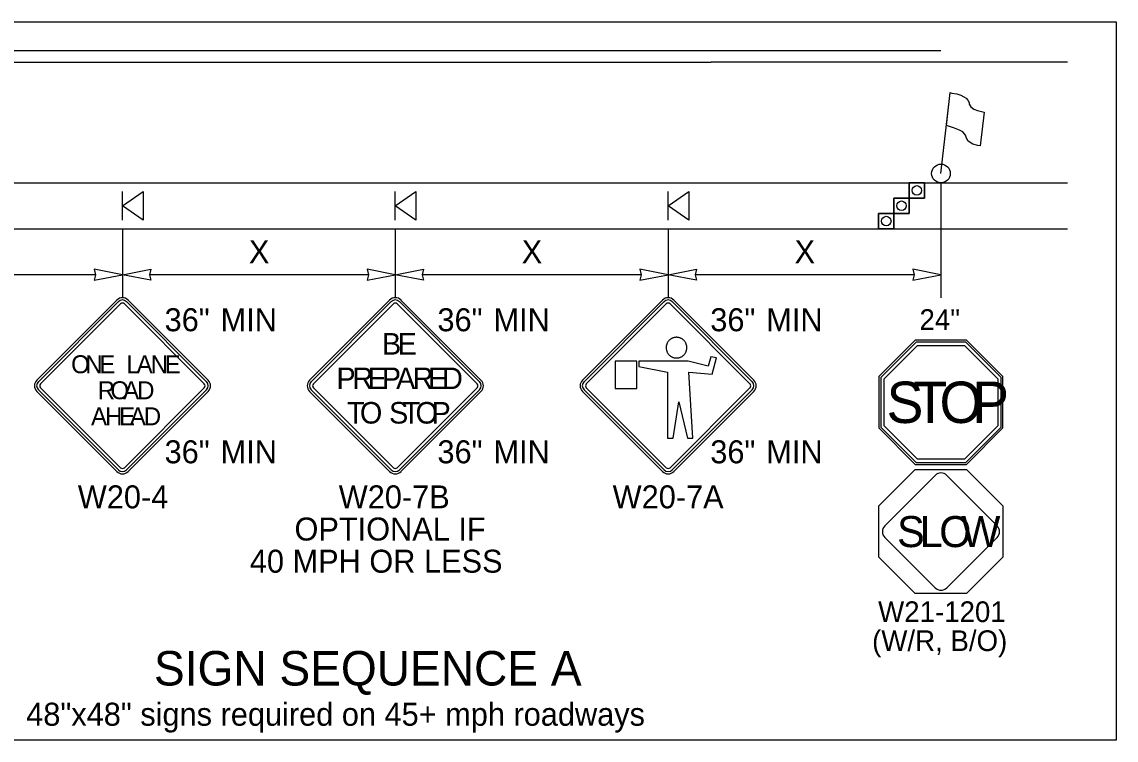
# Model space of a CAD drawing. Extents: x 99999.1 to 100095.7, y 99995 to 100010.7.
# Drawn here: x 100021.34 to 100025.15, y 100006.18 to 100008.68 of the extents above; entities that cross this region are included whole.
import ezdxf

# ---------------------------------------------------------------- set-up
doc = ezdxf.new("R2010")
doc.units = 0
for name, color, linetype in [('RD_ED_ShoulderPavedEdge', 7, 'Continuous'), ('RD_MK_LineDblYellowCenter', 7, 'Continuous'), ('RD_MK_LineEdgeWhite', 7, 'Continuous'), ('RD_MK_LineNoPass', 7, 'Continuous'), ('RD_MK_LineSkipCenter', 7, 'Continuous'), ('SH_DE_DetailHeading2Text', 7, 'Continuous'), ('TR_SN_ConstructionSigns', 7, 'Continuous'), ('TR_WZ_FlaggingStation', 7, 'Continuous'), ('TR_WZ_PortableSignMountBlk-Org', 7, 'Continuous'), ('TR_WZ_TrafficCone', 7, 'Continuous'), ('TR_WZ_WorkZoneDetails', 7, 'Continuous'), ('TR_WZ_WorkZoneTextCurrent', 7, 'Continuous')]:
    doc.layers.add(name, color=color, linetype=linetype)

msp = doc.modelspace()

# ---------------------------------------------------------------- linework, layer by layer
at = {"layer": 'RD_ED_ShoulderPavedEdge'}
msp.add_line((100020.3, 100007.9602), (100024.9804, 100007.9602), dxfattribs=at)
at = {"layer": 'RD_MK_LineDblYellowCenter'}
for p, q in [((100020.3, 100008.5802), (100023.7402, 100008.5802)), ((100020.3, 100008.5402), (100023.7402, 100008.5402))]:
    msp.add_line(p, q, dxfattribs=at)
at = {"layer": 'RD_MK_LineEdgeWhite'}
msp.add_line((100020.3, 100008.1202), (100024.9804, 100008.1202), dxfattribs=at)
at = {"layer": 'RD_MK_LineNoPass'}
msp.add_line((100023.7402, 100008.5802), (100024.5402, 100008.5802), dxfattribs=at)
at = {"layer": 'RD_MK_LineSkipCenter'}
msp.add_lwpolyline([(100024.9804, 100008.5402), (100023.7402, 100008.5402)], dxfattribs=at)
at = {"layer": 'TR_SN_ConstructionSigns'}
for p, q in [((100021.6703, 100007.712), (100021.3919, 100007.4336)), ((100021.9885, 100007.4336), (100021.71, 100007.712)), ((100022.6203, 100007.712), (100022.3419, 100007.4336)), ((100022.9385, 100007.4336), (100022.66, 100007.712)), ((100023.5703, 100007.712), (100023.2919, 100007.4336)), ((100023.8885, 100007.4336), (100023.61, 100007.712)), ((100021.6758, 100007.7065), (100021.3974, 100007.428)), ((100021.4051, 100007.4203), (100021.6835, 100007.6987)), ((100021.6968, 100007.6987), (100021.9752, 100007.4203)), ((100021.9829, 100007.428), (100021.7045, 100007.7065)), ((100022.6258, 100007.7065), (100022.3474, 100007.428)), ((100022.3551, 100007.4203), (100022.6335, 100007.6987)), ((100022.6468, 100007.6987), (100022.9252, 100007.4203)), ((100022.9329, 100007.428), (100022.6545, 100007.7065)), ((100023.5758, 100007.7065), (100023.2974, 100007.428)), ((100023.3051, 100007.4203), (100023.5835, 100007.6987)), ((100023.5968, 100007.6987), (100023.8752, 100007.4203)), ((100023.8829, 100007.428), (100023.6045, 100007.7065)), ((100023.5858, 100007.5595), (100023.5852, 100007.5577)), ((100023.5865, 100007.5613), (100023.5858, 100007.5595)), ((100023.5873, 100007.563), (100023.5865, 100007.5613)), ((100023.5883, 100007.5647), (100023.5873, 100007.563)), ((100023.5894, 100007.5664), (100023.5883, 100007.5647)), ((100023.5904, 100007.5679), (100023.5894, 100007.5664)), ((100023.5916, 100007.5694), (100023.5904, 100007.5679)), ((100023.5929, 100007.5709), (100023.5916, 100007.5694)), ((100023.5942, 100007.5722), (100023.5929, 100007.5709)), ((100023.5956, 100007.5735), (100023.5942, 100007.5722)), ((100023.5971, 100007.5747), (100023.5956, 100007.5735)), ((100023.5986, 100007.5759), (100023.5971, 100007.5747)), ((100023.6002, 100007.5769), (100023.5986, 100007.5759)), ((100023.6019, 100007.5779), (100023.6002, 100007.5769)), ((100023.6036, 100007.5788), (100023.6019, 100007.5779)), ((100023.6053, 100007.5796), (100023.6036, 100007.5788)), ((100023.6071, 100007.5803), (100023.6053, 100007.5796)), ((100023.6089, 100007.5809), (100023.6071, 100007.5803)), ((100023.6108, 100007.5814), (100023.6089, 100007.5809)), ((100023.6127, 100007.5818), (100023.6108, 100007.5814)), ((100023.6146, 100007.5821), (100023.6127, 100007.5818)), ((100023.6164, 100007.5823), (100023.6146, 100007.5821)), ((100023.6184, 100007.5824), (100023.6164, 100007.5823)), ((100023.6203, 100007.5824), (100023.6184, 100007.5824)), ((100023.6222, 100007.5823), (100023.6203, 100007.5824)), ((100023.6241, 100007.5821), (100023.6222, 100007.5823)), ((100023.626, 100007.5818), (100023.6241, 100007.5821)), ((100023.6279, 100007.5814), (100023.626, 100007.5818)), ((100023.6297, 100007.5809), (100023.6279, 100007.5814)), ((100023.6316, 100007.5803), (100023.6297, 100007.5809)), ((100023.6333, 100007.5796), (100023.6316, 100007.5803)), ((100023.6351, 100007.5788), (100023.6333, 100007.5796)), ((100023.6368, 100007.5779), (100023.6351, 100007.5788)), ((100023.6385, 100007.5769), (100023.6368, 100007.5779)), ((100023.64, 100007.5759), (100023.6385, 100007.5769)), ((100023.6416, 100007.5747), (100023.64, 100007.5759)), ((100023.643, 100007.5735), (100023.6416, 100007.5747)), ((100023.6445, 100007.5722), (100023.643, 100007.5735)), ((100023.6458, 100007.5709), (100023.6445, 100007.5722)), ((100023.647, 100007.5694), (100023.6458, 100007.5709)), ((100023.6482, 100007.5679), (100023.647, 100007.5694)), ((100023.6494, 100007.5664), (100023.6482, 100007.5679)), ((100023.6504, 100007.5647), (100023.6494, 100007.5664)), ((100023.6513, 100007.563), (100023.6504, 100007.5647)), ((100023.6521, 100007.5613), (100023.6513, 100007.563)), ((100023.6529, 100007.5595), (100023.6521, 100007.5613)), ((100023.6535, 100007.5577), (100023.6529, 100007.5595)), ((100024.4506, 100007.5722), (100024.3241, 100007.4457)), ((100024.4534, 100007.5655), (100024.3308, 100007.4429)), ((100024.6295, 100007.5722), (100024.4506, 100007.5722)), ((100024.6267, 100007.5655), (100024.4534, 100007.5655)), ((100024.7493, 100007.4429), (100024.6267, 100007.5655)), ((100024.7561, 100007.4457), (100024.6295, 100007.5722)), ((100023.5835, 100007.5502), (100023.5833, 100007.5483)), ((100023.5833, 100007.5483), (100023.5833, 100007.5464)), ((100023.5833, 100007.5464), (100023.5833, 100007.5445)), ((100023.5833, 100007.5445), (100023.5835, 100007.5426)), ((100023.5838, 100007.5522), (100023.5835, 100007.5502)), ((100023.5835, 100007.5426), (100023.5838, 100007.5407)), ((100023.5842, 100007.554), (100023.5838, 100007.5522)), ((100023.5838, 100007.5407), (100023.5842, 100007.5388)), ((100023.5846, 100007.5559), (100023.5842, 100007.554)), ((100023.5842, 100007.5388), (100023.5846, 100007.5369)), ((100023.5852, 100007.5577), (100023.5846, 100007.5559)), ((100023.5846, 100007.5369), (100023.5852, 100007.5351)), ((100023.5852, 100007.5351), (100023.5858, 100007.5333)), ((100023.5858, 100007.5333), (100023.5865, 100007.5315)), ((100023.5865, 100007.5315), (100023.5873, 100007.5298)), ((100023.5873, 100007.5298), (100023.5883, 100007.5281)), ((100023.5883, 100007.5281), (100023.5894, 100007.5265)), ((100023.5894, 100007.5265), (100023.5904, 100007.5249)), ((100023.5904, 100007.5249), (100023.5916, 100007.5234)), ((100023.5916, 100007.5234), (100023.5929, 100007.522)), ((100023.5929, 100007.522), (100023.5942, 100007.5206)), ((100023.5942, 100007.5206), (100023.5956, 100007.5193)), ((100023.643, 100007.5193), (100023.6445, 100007.5206)), ((100023.6445, 100007.5206), (100023.6458, 100007.522)), ((100023.6458, 100007.522), (100023.647, 100007.5234)), ((100023.647, 100007.5234), (100023.6482, 100007.5249)), ((100023.6482, 100007.5249), (100023.6494, 100007.5265)), ((100023.6494, 100007.5265), (100023.6504, 100007.5281)), ((100023.6504, 100007.5281), (100023.6513, 100007.5298)), ((100023.6513, 100007.5298), (100023.6521, 100007.5315)), ((100023.6521, 100007.5315), (100023.6529, 100007.5333)), ((100023.6529, 100007.5333), (100023.6535, 100007.5351)), ((100023.6541, 100007.5559), (100023.6535, 100007.5577)), ((100023.6535, 100007.5351), (100023.6541, 100007.5369)), ((100023.6545, 100007.554), (100023.6541, 100007.5559)), ((100023.6541, 100007.5369), (100023.6545, 100007.5388)), ((100023.6549, 100007.5522), (100023.6545, 100007.554)), ((100023.6545, 100007.5388), (100023.6549, 100007.5407)), ((100023.6552, 100007.5502), (100023.6549, 100007.5522)), ((100023.6549, 100007.5407), (100023.6552, 100007.5426)), ((100023.6553, 100007.5483), (100023.6552, 100007.5502)), ((100023.6552, 100007.5426), (100023.6553, 100007.5445)), ((100023.6554, 100007.5464), (100023.6553, 100007.5483)), ((100023.6553, 100007.5445), (100023.6554, 100007.5464)), ((100024.3421, 100007.4383), (100024.4581, 100007.5542)), ((100024.4581, 100007.5542), (100024.6221, 100007.5542)), ((100024.6221, 100007.5542), (100024.7381, 100007.4383)), ((100023.4059, 100007.4991), (100023.4059, 100007.4044)), ((100023.4812, 100007.4991), (100023.4059, 100007.4991)), ((100023.4812, 100007.4044), (100023.4812, 100007.4991)), ((100023.6596, 100007.4991), (100023.4882, 100007.4991)), ((100023.4882, 100007.4991), (100023.4882, 100007.481)), ((100023.5956, 100007.5193), (100023.5971, 100007.5181)), ((100023.5971, 100007.5181), (100023.5986, 100007.5169)), ((100023.5986, 100007.5169), (100023.6002, 100007.5159)), ((100023.6002, 100007.5159), (100023.6019, 100007.5149)), ((100023.6019, 100007.5149), (100023.6036, 100007.514)), ((100023.6036, 100007.514), (100023.6053, 100007.5132)), ((100023.6053, 100007.5132), (100023.6071, 100007.5125)), ((100023.6071, 100007.5125), (100023.6089, 100007.5119)), ((100023.6089, 100007.5119), (100023.6108, 100007.5114)), ((100023.6108, 100007.5114), (100023.6127, 100007.511)), ((100023.6127, 100007.511), (100023.6146, 100007.5107)), ((100023.6146, 100007.5107), (100023.6164, 100007.5105)), ((100023.6164, 100007.5105), (100023.6184, 100007.5104)), ((100023.6184, 100007.5104), (100023.6203, 100007.5104)), ((100023.6203, 100007.5104), (100023.6222, 100007.5105)), ((100023.6222, 100007.5105), (100023.6241, 100007.5107)), ((100023.6241, 100007.5107), (100023.626, 100007.511)), ((100023.626, 100007.511), (100023.6279, 100007.5114)), ((100023.6279, 100007.5114), (100023.6297, 100007.5119)), ((100023.6297, 100007.5119), (100023.6316, 100007.5125)), ((100023.6316, 100007.5125), (100023.6333, 100007.5132)), ((100023.6333, 100007.5132), (100023.6351, 100007.514)), ((100023.6351, 100007.514), (100023.6368, 100007.5149)), ((100023.6368, 100007.5149), (100023.6385, 100007.5159)), ((100023.6385, 100007.5159), (100023.64, 100007.5169)), ((100023.64, 100007.5169), (100023.6416, 100007.5181)), ((100023.6416, 100007.5181), (100023.643, 100007.5193)), ((100023.7291, 100007.482), (100023.6596, 100007.4991)), ((100023.7388, 100007.5148), (100023.7291, 100007.482)), ((100023.7588, 100007.5112), (100023.7388, 100007.5148)), ((100023.7438, 100007.4544), (100023.7588, 100007.5112)), ((100023.4882, 100007.481), (100023.5877, 100007.4612)), ((100023.5877, 100007.4612), (100023.5877, 100007.2309)), ((100023.6759, 100007.2309), (100023.6628, 100007.4613)), ((100023.6628, 100007.4613), (100023.7438, 100007.4544)), ((100024.3241, 100007.4457), (100024.3241, 100007.2668)), ((100024.7561, 100007.2668), (100024.7561, 100007.4457)), ((100021.6835, 100007.1286), (100021.4051, 100007.4071)), ((100021.9752, 100007.4071), (100021.6968, 100007.1286)), ((100022.6335, 100007.1286), (100022.3551, 100007.4071)), ((100022.9252, 100007.4071), (100022.6468, 100007.1286)), ((100023.5835, 100007.1286), (100023.3051, 100007.4071)), ((100023.8752, 100007.4071), (100023.5968, 100007.1286)), ((100024.3308, 100007.4429), (100024.3308, 100007.2696)), ((100024.3421, 100007.2742), (100024.3421, 100007.4383)), ((100024.7381, 100007.4383), (100024.7381, 100007.2742)), ((100024.7493, 100007.2696), (100024.7493, 100007.4429)), ((100021.3919, 100007.3938), (100021.6703, 100007.1154)), ((100021.3974, 100007.3993), (100021.6758, 100007.1209)), ((100021.7045, 100007.1209), (100021.9829, 100007.3993)), ((100021.71, 100007.1154), (100021.9885, 100007.3938)), ((100022.3419, 100007.3938), (100022.6203, 100007.1154)), ((100022.3474, 100007.3993), (100022.6258, 100007.1209)), ((100022.6545, 100007.1209), (100022.9329, 100007.3993)), ((100022.66, 100007.1154), (100022.9385, 100007.3938)), ((100023.2919, 100007.3938), (100023.5703, 100007.1154)), ((100023.2974, 100007.3993), (100023.5758, 100007.1209)), ((100023.4059, 100007.4044), (100023.4812, 100007.4044)), ((100023.6045, 100007.1209), (100023.8829, 100007.3993)), ((100023.61, 100007.1154), (100023.8885, 100007.3938)), ((100023.6079, 100007.2309), (100023.6276, 100007.3576)), ((100023.6276, 100007.3576), (100023.6579, 100007.2309)), ((100024.3241, 100007.2668), (100024.4506, 100007.1402)), ((100024.3308, 100007.2696), (100024.4534, 100007.147)), ((100024.4581, 100007.1582), (100024.3421, 100007.2742)), ((100024.7381, 100007.2742), (100024.6221, 100007.1582)), ((100024.6267, 100007.147), (100024.7493, 100007.2696)), ((100024.6295, 100007.1402), (100024.7561, 100007.2668)), ((100023.5877, 100007.2309), (100023.6079, 100007.2309)), ((100023.6579, 100007.2309), (100023.6759, 100007.2309)), ((100024.4506, 100007.1402), (100024.6295, 100007.1402)), ((100024.4534, 100007.147), (100024.6267, 100007.147)), ((100024.6221, 100007.1582), (100024.4581, 100007.1582)), ((100024.5197, 100007.1019), (100024.3444, 100006.9266)), ((100024.7357, 100006.9266), (100024.5604, 100007.1019)), ((100024.3444, 100006.8859), (100024.5197, 100006.7106)), ((100024.5604, 100006.7106), (100024.7357, 100006.8859))]:
    msp.add_line(p, q, dxfattribs=at)
msp.add_lwpolyline([(100024.7561, 100006.9957), (100024.7561, 100006.8168), (100024.6295, 100006.6902), (100024.4506, 100006.6902), (100024.3241, 100006.8168), (100024.3241, 100006.9957), (100024.4506, 100007.1222), (100024.6295, 100007.1222)], close=True, dxfattribs=at)
for centre, radius, start, end in [((100021.6902, 100007.6921), 0.0281, 45, 135), ((100021.6902, 100007.6921), 0.0203, 45, 135), ((100022.6402, 100007.6921), 0.0281, 45, 135), ((100022.6402, 100007.6921), 0.0203, 45, 135), ((100023.5902, 100007.6921), 0.0281, 45, 135), ((100023.5902, 100007.6921), 0.0203, 45, 135), ((100021.6902, 100007.6921), 0.00937, 45, 135), ((100022.6402, 100007.6921), 0.00937, 45, 135), ((100023.5902, 100007.6921), 0.00937, 45, 135), ((100021.4117, 100007.4137), 0.0281, 135, 225), ((100021.4117, 100007.4137), 0.0203, 135, 225), ((100021.4117, 100007.4137), 0.00937, 135, 225), ((100021.9686, 100007.4137), 0.00937, 315, 45), ((100021.9686, 100007.4137), 0.0203, 315, 45), ((100021.9686, 100007.4137), 0.0281, 315, 45), ((100022.3617, 100007.4137), 0.0281, 135, 225), ((100022.3617, 100007.4137), 0.0203, 135, 225), ((100022.3617, 100007.4137), 0.00937, 135, 225), ((100022.9186, 100007.4137), 0.00937, 315, 45), ((100022.9186, 100007.4137), 0.0203, 315, 45), ((100022.9186, 100007.4137), 0.0281, 315, 45), ((100023.3117, 100007.4137), 0.0281, 135, 225), ((100023.3117, 100007.4137), 0.0203, 135, 225), ((100023.3117, 100007.4137), 0.00937, 135, 225), ((100023.8686, 100007.4137), 0.00937, 315, 45), ((100023.8686, 100007.4137), 0.0203, 315, 45), ((100023.8686, 100007.4137), 0.0281, 315, 45), ((100021.6902, 100007.1353), 0.0281, 225, 315), ((100021.6902, 100007.1353), 0.0203, 225, 315), ((100021.6902, 100007.1353), 0.00937, 225, 315), ((100022.6402, 100007.1353), 0.0281, 225, 315), ((100022.6402, 100007.1353), 0.0203, 225, 315), ((100022.6402, 100007.1353), 0.00937, 225, 315), ((100023.5902, 100007.1353), 0.0281, 225, 315), ((100023.5902, 100007.1353), 0.0203, 225, 315), ((100023.5902, 100007.1353), 0.00937, 225, 315), ((100024.5401, 100007.0815), 0.0288, 45, 135), ((100024.3648, 100006.9062), 0.0288, 135, 225), ((100024.7153, 100006.9062), 0.0288, 315, 45), ((100024.5401, 100006.731), 0.0288, 225, 315)]:
    msp.add_arc(centre, radius, start, end, dxfattribs=at)
at = {"layer": 'TR_WZ_FlaggingStation'}
for p, q in [((100024.5402, 100008.1527), (100024.5722, 100008.4337)), ((100024.5592, 100008.3196), (100024.5723, 100008.434)), ((100024.6902, 100008.3662), (100024.6769, 100008.249)), ((100024.5592, 100008.3196), (100024.5592, 100008.3196))]:
    msp.add_line(p, q, dxfattribs=at)
for points in [[(100024.5723, 100008.434), (100024.578, 100008.4327), (100024.5958, 100008.4293), (100024.6097, 100008.4251), (100024.6193, 100008.419), (100024.6279, 100008.4143), (100024.6335, 100008.4075), (100024.6378, 100008.3996), (100024.6383, 100008.3934), (100024.6437, 100008.3842), (100024.6545, 100008.3768), (100024.6669, 100008.3716), (100024.6902, 100008.3662)], [(100024.6769, 100008.249), (100024.6687, 100008.2504), (100024.6511, 100008.255), (100024.6354, 100008.2655), (100024.6289, 100008.2761), (100024.625, 100008.2864), (100024.6159, 100008.2973), (100024.6049, 100008.3035), (100024.5876, 100008.3106), (100024.5592, 100008.3196)]]:
    msp.add_lwpolyline(points, dxfattribs=at)
msp.add_circle((100024.5402, 100008.1527), 0.0325, dxfattribs=at)
at = {"layer": 'TR_WZ_PortableSignMountBlk-Org'}
for p, q in [((100021.6902, 100007.9902), (100021.6902, 100008.0902)), ((100022.6402, 100007.9902), (100022.6402, 100008.0902)), ((100023.5902, 100007.9902), (100023.5902, 100008.0902))]:
    msp.add_line(p, q, dxfattribs=at)
for points in [[(100021.6902, 100008.0401), (100021.762, 100008.0902), (100021.762, 100007.9902)], [(100022.6402, 100008.0401), (100022.712, 100008.0902), (100022.712, 100007.9902)], [(100023.5902, 100008.0401), (100023.662, 100008.0902), (100023.662, 100007.9902)]]:
    msp.add_lwpolyline(points, close=True, dxfattribs=at)
at = {"layer": 'TR_WZ_TrafficCone'}
for points in [[(100024.4295, 100008.1202), (100024.4828, 100008.1202), (100024.4828, 100008.0669), (100024.4295, 100008.0669), (100024.4295, 100008.1202)], [(100024.4295, 100008.0669), (100024.4828, 100008.0669), (100024.4828, 100008.1202), (100024.4295, 100008.1202), (100024.4295, 100008.0669)], [(100024.3762, 100008.0669), (100024.4295, 100008.0669), (100024.4295, 100008.0136), (100024.3762, 100008.0136), (100024.3762, 100008.0669)], [(100024.3762, 100008.0136), (100024.4295, 100008.0136), (100024.4295, 100008.0669), (100024.3762, 100008.0669), (100024.3762, 100008.0136)], [(100024.3228, 100008.0136), (100024.3762, 100008.0136), (100024.3762, 100007.9602), (100024.3228, 100007.9602), (100024.3228, 100008.0136)], [(100024.3228, 100007.9602), (100024.3762, 100007.9602), (100024.3762, 100008.0136), (100024.3228, 100008.0136), (100024.3228, 100007.9602)]]:
    msp.add_lwpolyline(points, dxfattribs=at)
for centre in [(100024.4562, 100008.0936), (100024.4028, 100008.0402), (100024.3495, 100007.9869)]:
    msp.add_circle(centre, 0.0167, dxfattribs=at)
at = {"layer": 'TR_WZ_WorkZoneDetails'}
for p, q in [((100024.5402, 100008.1202), (100024.5402, 100007.7202)), ((100021.6902, 100007.9602), (100021.6902, 100007.7202)), ((100022.6402, 100007.9602), (100022.6402, 100007.7202)), ((100023.5902, 100007.9602), (100023.5902, 100007.7202)), ((100021.5964, 100007.8002), (100020.8339, 100007.8002)), ((100022.5464, 100007.8002), (100021.7839, 100007.8002)), ((100023.4964, 100007.8002), (100022.7339, 100007.8002)), ((100024.4464, 100007.8002), (100023.6839, 100007.8002))]:
    msp.add_line(p, q, dxfattribs=at)
for points in [[(100021.6902, 100007.8002), (100021.5919, 100007.8195), (100021.5964, 100007.8002), (100021.5919, 100007.781)], [(100021.6902, 100007.8002), (100021.7884, 100007.8195), (100021.7839, 100007.8002), (100021.7884, 100007.781)], [(100022.6402, 100007.8002), (100022.5419, 100007.8195), (100022.5464, 100007.8002), (100022.5419, 100007.781)], [(100022.6402, 100007.8002), (100022.7384, 100007.8195), (100022.7339, 100007.8002), (100022.7384, 100007.781)], [(100023.5902, 100007.8002), (100023.4919, 100007.8195), (100023.4964, 100007.8002), (100023.4919, 100007.781)], [(100023.5902, 100007.8002), (100023.6884, 100007.8195), (100023.6839, 100007.8002), (100023.6884, 100007.781)], [(100024.5402, 100007.8002), (100024.4419, 100007.8195), (100024.4464, 100007.8002), (100024.4419, 100007.781)]]:
    msp.add_lwpolyline(points, close=True, dxfattribs=at)
at = {"layer": 'TR_WZ_WorkZoneTextCurrent'}
msp.add_lwpolyline([(100020.1, 100008.6802), (100025.15, 100008.6802), (100025.15, 100006.1804), (100020.1, 100006.1804)], close=True, dxfattribs=at)

# ---------------------------------------------------------------- texts
at = {"layer": 'SH_DE_DetailHeading2Text'}
msp.add_text('SIGN SEQUENCE A', height=0.12, rotation=360, dxfattribs=at).set_placement((100021.7998, 100006.3705))
at = {"layer": 'TR_SN_ConstructionSigns'}
for s, height, p in [('36"', 0.08, (100021.8369, 100007.6035)), ('MIN', 0.08, (100022.0319, 100007.6035)), ('36"', 0.08, (100022.7869, 100007.6035)), ('MIN', 0.08, (100022.9819, 100007.6035)), ('36"', 0.08, (100023.7369, 100007.6035)), ('MIN', 0.08, (100023.9319, 100007.6035)), ('36"', 0.08, (100021.8369, 100007.1439)), ('MIN', 0.08, (100022.0319, 100007.1439)), ('36"', 0.08, (100022.7869, 100007.1439)), ('MIN', 0.08, (100022.9819, 100007.1439)), ('36"', 0.08, (100023.7369, 100007.1439)), ('MIN', 0.08, (100023.9319, 100007.1439)), ('W20-4', 0.08, (100021.5347, 100006.9871)), ('W20-7B', 0.08, (100022.4432, 100006.9871)), ('W20-7A', 0.08, (100023.3969, 100006.9871)), ('OPTIONAL IF', 0.08, (100022.2892, 100006.8751)), ('40 MPH OR LESS', 0.08, (100022.1337, 100006.7631)), ('W21-1201', 0.072, (100024.3213, 100006.5913)), ('(W/R, B/O)', 0.072, (100024.3004, 100006.4905))]:
    msp.add_text(s, height=height, rotation=360, dxfattribs=at).set_placement(p)
for s, height, p in [('24"', 0.072, (100024.4654, 100007.6082)), ('B', 0.075, (100022.5939, 100007.5222)), ('E', 0.075, (100022.6482, 100007.5222)), ('O', 0.0625, (100021.5114, 100007.4574)), ('N', 0.0625, (100021.5608, 100007.4574)), ('E', 0.0625, (100021.6095, 100007.4574)), ('L', 0.0625, (100021.7039, 100007.4574)), ('A', 0.0625, (100021.7395, 100007.4574)), ('N', 0.0625, (100021.7883, 100007.4574)), ('E', 0.0625, (100021.837, 100007.4574)), ('P', 0.075, (100022.4353, 100007.4022)), ('R', 0.075, (100022.4905, 100007.4022)), ('E', 0.075, (100022.5437, 100007.4022)), ('P', 0.075, (100022.5932, 100007.4022)), ('A', 0.075, (100022.6431, 100007.4022)), ('R', 0.075, (100022.7004, 100007.4022)), ('E', 0.075, (100022.7536, 100007.4022)), ('D', 0.075, (100022.8031, 100007.4022)), ('R', 0.0625, (100021.6039, 100007.3668)), ('O', 0.0625, (100021.6483, 100007.3668)), ('A', 0.0625, (100021.6927, 100007.3668)), ('D', 0.0625, (100021.7414, 100007.3668)), ('S', 0.144, (100024.3507, 100007.2842)), ('T', 0.144, (100024.4443, 100007.2842)), ('O', 0.144, (100024.535, 100007.2842)), ('P', 0.144, (100024.6488, 100007.2842)), ('A', 0.0625, (100021.5808, 100007.2762)), ('H', 0.0625, (100021.6295, 100007.2762)), ('E', 0.0625, (100021.6783, 100007.2762)), ('A', 0.0625, (100021.7158, 100007.2762)), ('D', 0.0625, (100021.7645, 100007.2762)), ('T', 0.075, (100022.4719, 100007.2822)), ('O', 0.075, (100022.517, 100007.2822)), ('S', 0.075, (100022.6185, 100007.2822)), ('T', 0.075, (100022.6656, 100007.2822)), ('O', 0.075, (100022.7107, 100007.2822)), ('P', 0.075, (100022.7664, 100007.2822)), ('S', 0.108, (100024.3873, 100006.8522)), ('L', 0.108, (100024.4661, 100006.8522)), ('O', 0.108, (100024.5341, 100006.8522)), ('W', 0.108, (100024.6108, 100006.8522))]:
    msp.add_text(s, height=height, dxfattribs=at).set_placement(p)
at = {"layer": 'TR_WZ_WorkZoneTextCurrent'}
for p in [(100022.1304, 100007.8402), (100023.0804, 100007.8402), (100024.0304, 100007.8402)]:
    msp.add_text('X', height=0.08, rotation=360, dxfattribs=at).set_placement(p)
msp.add_text('48"x48" signs required on 45+ mph roadways', height=0.08, dxfattribs=at).set_placement((100021.3551, 100006.2305))

doc.saveas('drawing.dxf')
